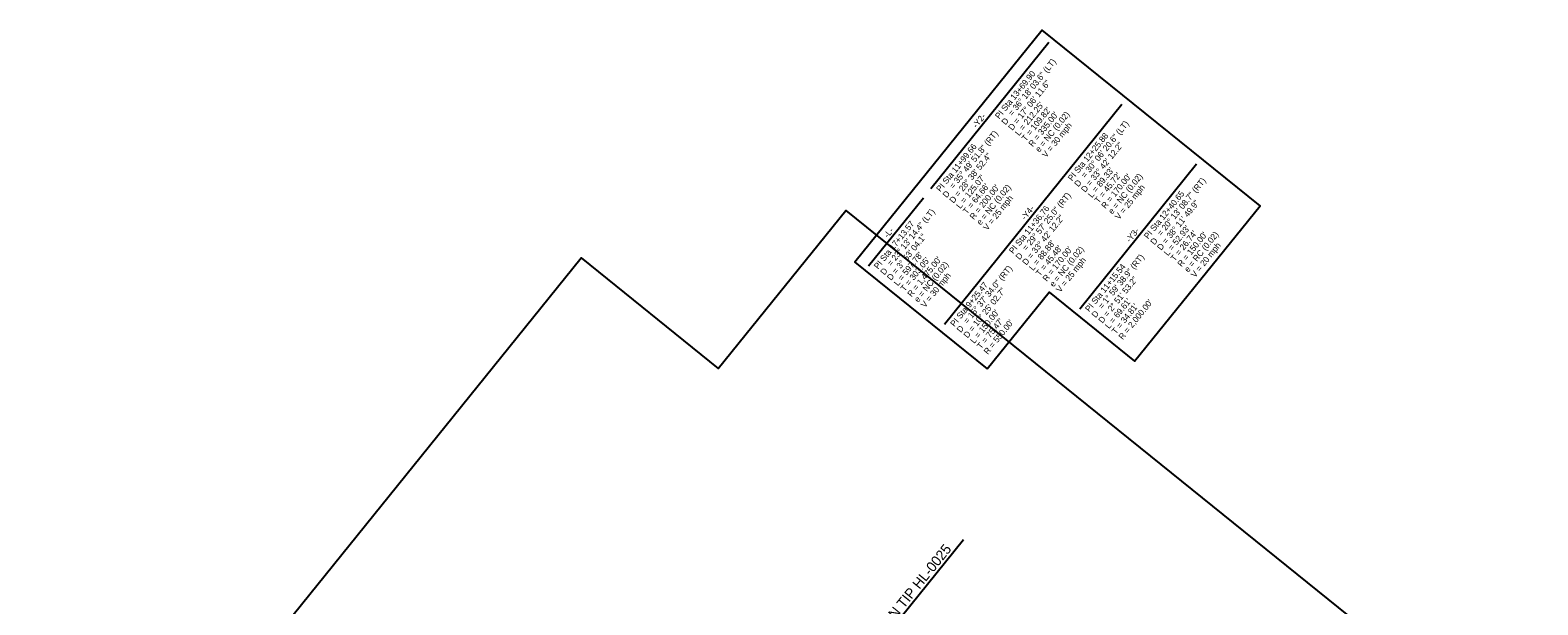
# Model space of a CAD drawing. Extents: x 1487008 to 1489561, y 497293 to 500195.
# Drawn here: x 1488075 to 1489561, y 499628 to 500195 of the extents above; entities that cross this region are included whole.
import ezdxf

# ---------------------------------------------------------------- set-up
doc = ezdxf.new("R2010")
doc.units = 0
for name, color, linetype in [('Prop Grid Mask', 7, 'Continuous'), ('Prop Horizontal Alignment Curve and Spiral Data', 7, 'Continuous'), ('Prop Horizontal Alignment Station Label', 7, 'Continuous'), ('Scratch_Level_5', 7, 'Continuous')]:
    doc.layers.add(name, color=color, linetype=linetype)

msp = doc.modelspace()

# ---------------------------------------------------------------- linework, layer by layer
at = {"layer": 'Prop Grid Mask'}
msp.add_lwpolyline([(1489018.6, 499860.6), (1489079.5, 499936.1), (1489163.8, 499868.1), (1489287.4, 500021.4), (1489072.6, 500194.6), (1488888.1, 499965.8)], close=True, dxfattribs=at)
at = {"layer": 'Prop Horizontal Alignment Curve and Spiral Data'}
for p, q in [((1488962.9, 500038.3), (1489079.4, 500182.7)), ((1488976.3, 499904.7), (1489151.2, 500121.6)), ((1489109.7, 499919.9), (1489224.9, 500062.8)), ((1488901.5, 499962.1), (1488955.6, 500029.3))]:
    msp.add_line(p, q, dxfattribs=at)
at = {"layer": 'Prop Horizontal Alignment Station Label'}
msp.add_line((1488846.3, 499507.9), (1488995, 499692.2), dxfattribs=at)
at = {"layer": 'Scratch_Level_5'}
msp.add_lwpolyline([(1488075.1, 499296.3), (1488618.3, 499969.9), (1488753.4, 499860.9), (1488879, 500016.6), (1489561.3, 499466.4), (1488882.1, 498624.3), (1488882.1, 498624.3)], dxfattribs=at)

# ---------------------------------------------------------------- texts
at = {"layer": 'Prop Horizontal Alignment Curve and Spiral Data'}
for s, rotation, p in [('= 36%%d 18\' 03.6" (LT)', 51.1156, (1489043.3, 500109.4)), ('PI Sta 13+69.90', 51.1156, (1489030.3, 500106.5)), ('D = 17%%d 06\' 11.6"', 51.1156, (1489043.3, 500095.2)), ("L = 212.25'", 51.1156, (1489049.9, 500089.9)), ("T = 109.82'", 51.1156, (1489056.6, 500084.5)), ("R = 335.00'", 51.1156, (1489063.3, 500079.1)), ('e = NC (0.02)', 51.1156, (1489069.9, 500073.7)), ('-Y2-', 51.1156, (1489008, 500097.6)), ('D', 51.1156, (1489036.6, 500100.6)), ('V = 30 mph', 51.1156, (1489076.6, 500068.3)), ('= 30%%d 06\' 20.6" (LT)', 51.1164, (1489115.1, 500048.2)), ('PI Sta 11+99.66', 51.1156, (1488972.3, 500034.6)), ('= 35%%d 49\' 51.8" (RT)', 51.1156, (1488985.3, 500037.5)), ('PI Sta 12+25.88', 51.1164, (1489102.1, 500045.3)), ('D = 33%%d 42\' 12.2"', 51.1164, (1489115.1, 500034.1)), ('D = 28%%d 38\' 52.4"', 51.1156, (1488985.3, 500023.4)), ("L = 125.07'", 51.1156, (1488992, 500018)), ("L = 89.33'", 51.1164, (1489121.8, 500028.8)), ("T = 45.72'", 51.1164, (1489128.4, 500023.4)), ("R = 170.00'", 51.1164, (1489135.1, 500018)), ('e = NC (0.02)', 51.1156, (1489141.8, 500012.6)), ("T = 64.66'", 51.1156, (1488998.6, 500012.6)), ("R = 200.00'", 51.1156, (1489005.3, 500007.2)), ('e = NC (0.02)', 51.1156, (1489012, 500001.8)), ('D', 51.1164, (1489108.4, 500039.5)), ('V = 25 mph', 51.1156, (1489148.5, 500007.2)), ('= 20%%d 13\' 08.7" (RT)', 51.1156, (1489190.1, 499991)), ('D', 51.1156, (1488978.6, 500028.7)), ('V = 25 mph', 51.1156, (1489018.6, 499996.5)), ('= 29%%d 57\' 25.0" (RT)', 51.1964, (1489057.2, 499976.4)), ('PI Sta 12+40.65', 51.1156, (1489177.1, 499988.1)), ('D = 38%%d 11\' 49.9"', 51.1156, (1489190, 499976.9)), ('= 23%%d 13\' 14.4" (LT)', 51.1156, (1488923.9, 499961.3)), ('PI Sta 11+36.76', 51.1964, (1489044.1, 499973.5)), ('D = 33%%d 42\' 12.2"', 51.1964, (1489057.1, 499962.3)), ('-Y4-', 51.1156, (1489055.9, 500006.8)), ('PI Sta 17+13.57', 51.1156, (1488910.9, 499958.4)), ('-L-', 51.1156, (1488920.6, 499989.2)), ('D = 3%%d 53\' 04.1"', 51.1156, (1488923.8, 499947.2)), ('-Y3-', 51.1156, (1489159.2, 499984.7)), ("L = 52.93'", 51.1156, (1489196.7, 499971.5)), ("T = 26.74'", 51.1156, (1489203.4, 499966.1)), ("R = 150.00'", 51.1156, (1489210.1, 499960.7)), ('e = RC (0.02)', 51.1156, (1489216.7, 499955.3)), ("L = 88.88'", 51.1964, (1489063.8, 499956.9)), ("T = 45.48'", 51.1964, (1489070.5, 499951.5)), ("R = 170.00'", 51.1964, (1489077.2, 499946.2)), ('e = NC (0.02)', 51.1156, (1489083.9, 499940.8)), ('D', 51.1156, (1489183.4, 499982.3)), ('V = 20 mph', 51.1156, (1489223.4, 499950)), ("L = 597.78'", 51.1156, (1488930.5, 499941.8)), ("T = 303.05'", 51.1156, (1488937.2, 499936.4)), ("R = 1,475.00'", 51.1156, (1488943.9, 499931)), ('e = NC (0.02)', 51.1156, (1488950.5, 499925.7)), ('D', 51.1964, (1489050.5, 499967.6)), ('V = 25 mph', 51.1156, (1489090.5, 499935.4)), ('PI Sta 11+15.54', 51.1156, (1489119.1, 499916.2)), ('= 1%%d 59\' 38.9" (RT)', 51.1156, (1489132.1, 499919.1)), ('D', 51.1156, (1488917.2, 499952.6)), ('V = 30 mph', 51.1156, (1488957.2, 499920.3)), ('= 15%%d 37\' 34.0" (RT)', 51.1156, (1488999.2, 499904.5)), ('D = 2%%d 51\' 53.2"', 51.1156, (1489132.1, 499905)), ('PI Sta 9+25.47', 51.1156, (1488986.2, 499901.6)), ('D = 10%%d 25\' 02.7"', 51.1156, (1488999.2, 499890.4)), ("L = 150.00'", 51.1156, (1489005.8, 499885)), ("L = 69.61'", 51.1156, (1489138.7, 499899.6)), ("T = 34.81'", 51.1156, (1489145.4, 499894.2)), ("R = 2,000.00'", 51.1156, (1489152.1, 499888.8)), ("T = 75.47'", 51.1156, (1489012.5, 499879.6)), ("R = 550.00'", 51.1156, (1489019.2, 499874.2)), ('D', 51.1156, (1489125.4, 499910.4)), ('D', 51.1156, (1488992.5, 499895.8))]:
    msp.add_text(s, height=6, rotation=rotation, dxfattribs=at).set_placement(p)
at = {"layer": 'Prop Horizontal Alignment Station Label'}
msp.add_text('END CONSTRUCTION TIP HL-0025', height=10, rotation=51.1156, dxfattribs=at).set_placement((1488846.3, 499511.9))

doc.saveas('drawing.dxf')
